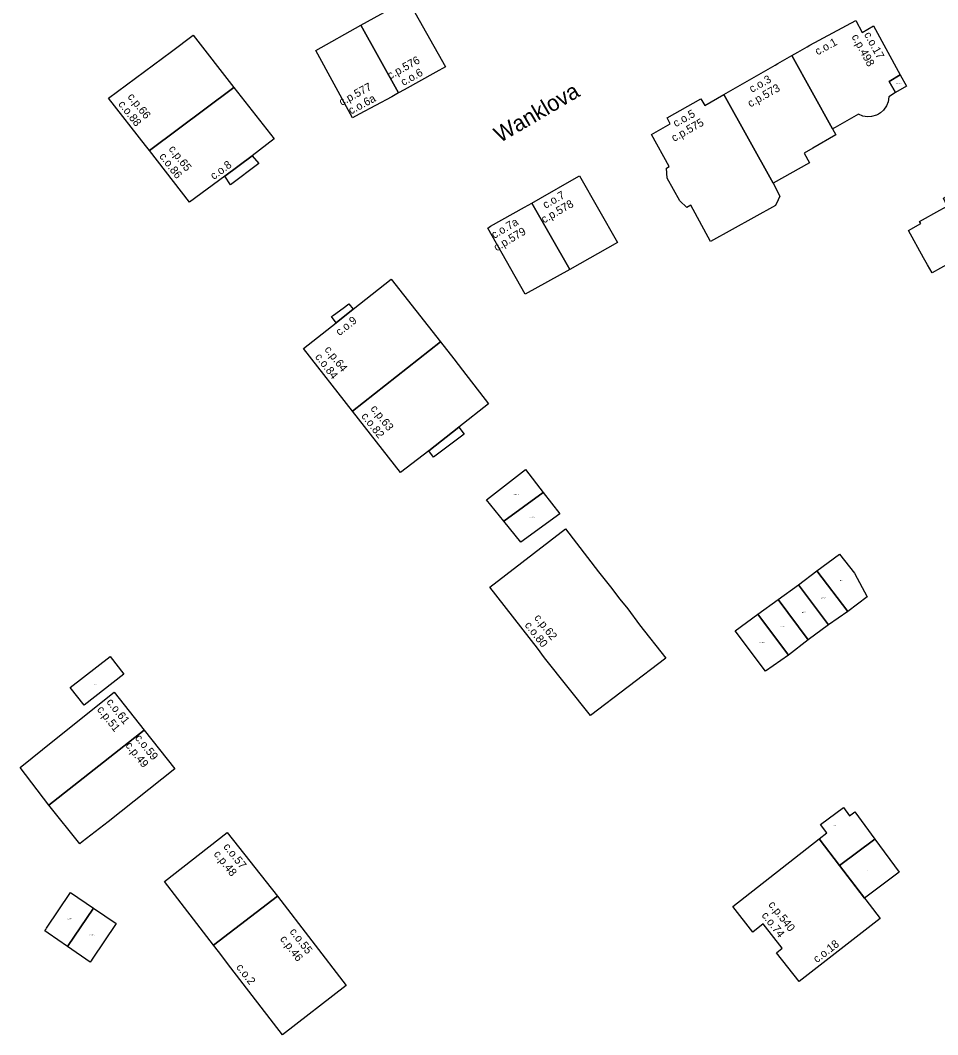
# Model space of a CAD drawing. Extents: x -600391 to -599491, y -1160176 to -1159402.
# Drawn here: x -600327.9 to -600213.3, y -1160067.8 to -1159941 of the extents above; entities that cross this region are included whole.
import ezdxf

# ---------------------------------------------------------------- set-up
doc = ezdxf.new("R2010")
doc.units = 0
for name, color, linetype in [('Level 10', 7, 'Continuous'), ('Level 11', 7, 'Continuous'), ('Level 12', 7, 'Continuous'), ('Level 24', 7, 'Continuous'), ('Level 25', 7, 'Continuous'), ('Level 61', 7, 'Continuous'), ('Level 62', 7, 'Continuous')]:
    doc.layers.add(name, color=color, linetype=linetype)

msp = doc.modelspace()

# ---------------------------------------------------------------- linework, layer by layer
at = {"layer": 'Level 61'}
for points in [[(-600285.36, -1159941.63), (-600279.55, -1159938.41)], [(-600279.55, -1159938.41), (-600274.78, -1159946.87)], [(-600229.25, -1159944.16), (-600223.53, -1159941.07)], [(-600223.53, -1159941.07), (-600222.73, -1159942.57)], [(-600290.98, -1159944.83), (-600285.36, -1159941.63)], [(-600285.36, -1159941.63), (-600280.65, -1159950.09)], [(-600280.65, -1159950.09), (-600285.36, -1159941.63)], [(-600222.73, -1159942.57), (-600221.32, -1159941.73)], [(-600221.32, -1159941.73), (-600217.98, -1159947.85)], [(-600309.01, -1159944.93), (-600306.29, -1159942.91)], [(-600306.29, -1159942.91), (-600301.22, -1159949.45)], [(-600312.4, -1159947.44), (-600309.01, -1159944.93)], [(-600286.39, -1159953.23), (-600290.98, -1159944.83)], [(-600230.77, -1159945.02), (-600229.6, -1159944.36)], [(-600229.6, -1159944.36), (-600229.25, -1159944.16)], [(-600233.25, -1159946.44), (-600231.52, -1159945.45)], [(-600231.52, -1159945.45), (-600230.77, -1159945.02)], [(-600231.52, -1159945.45), (-600226.43, -1159954.6)], [(-600226.43, -1159954.6), (-600231.52, -1159945.45)], [(-600316.88, -1159950.78), (-600312.4, -1159947.44)], [(-600275.98, -1159947.53), (-600279.95, -1159949.71)], [(-600274.78, -1159946.87), (-600275.98, -1159947.53)], [(-600240.02, -1159950.31), (-600233.6, -1159946.64)], [(-600233.6, -1159946.64), (-600233.25, -1159946.44)], [(-600219.36, -1159948.67), (-600217.98, -1159947.85)], [(-600217.98, -1159947.85), (-600219.36, -1159948.67)], [(-600218.56, -1159950.08), (-600219.36, -1159948.67)], [(-600219.36, -1159948.67), (-600218.56, -1159950.08)], [(-600217.98, -1159947.85), (-600217.19, -1159949.29)], [(-600301.22, -1159949.45), (-600311.77, -1159957.33)], [(-600311.77, -1159957.33), (-600301.22, -1159949.45)], [(-600301.22, -1159949.45), (-600296.21, -1159955.87)], [(-600279.95, -1159949.71), (-600280.65, -1159950.09)], [(-600218.56, -1159950.08), (-600219.4, -1159950.61)], [(-600217.19, -1159949.29), (-600218.56, -1159950.08)], [(-600312.28, -1159956.68), (-600316.88, -1159950.78)], [(-600281.5, -1159950.59), (-600285.57, -1159952.79)], [(-600280.65, -1159950.09), (-600281.5, -1159950.59)], [(-600247.1, -1159953.23), (-600242.88, -1159950.86)], [(-600242.88, -1159950.86), (-600242.4, -1159951.67)], [(-600242.4, -1159951.67), (-600240.02, -1159950.31)], [(-600233.84, -1159961.39), (-600240.02, -1159950.31)], [(-600240.02, -1159950.31), (-600233.84, -1159961.39)], [(-600219.48, -1159951.21), (-600219.7, -1159951.74)], [(-600219.4, -1159950.61), (-600219.48, -1159951.21)], [(-600220.44, -1159952.6), (-600220.68, -1159952.76)], [(-600220.05, -1159952.26), (-600220.44, -1159952.6)], [(-600219.7, -1159951.74), (-600220.05, -1159952.26)], [(-600285.57, -1159952.79), (-600286.39, -1159953.23)], [(-600246.71, -1159953.98), (-600247.1, -1159953.23)], [(-600223.18, -1159952.76), (-600226.09, -1159954.44)], [(-600222.62, -1159953), (-600223.18, -1159952.76)], [(-600222.04, -1159953.09), (-600222.62, -1159953)], [(-600221.54, -1159953.06), (-600222.04, -1159953.09)], [(-600220.93, -1159952.89), (-600221.54, -1159953.06)], [(-600220.68, -1159952.76), (-600220.93, -1159952.89)], [(-600249.03, -1159955.33), (-600246.71, -1159953.98)], [(-600226.09, -1159954.44), (-600226.43, -1159954.6)], [(-600226.43, -1159954.6), (-600226.02, -1159955.35)], [(-600296.21, -1159955.87), (-600298.92, -1159957.98)], [(-600246.84, -1159959.32), (-600249.03, -1159955.33)], [(-600226.02, -1159955.35), (-600228.9, -1159957.03)], [(-600311.77, -1159957.33), (-600312.28, -1159956.68)], [(-600306.75, -1159963.77), (-600311.77, -1159957.33)], [(-600228.9, -1159957.03), (-600229.98, -1159957.66)], [(-600229.98, -1159957.66), (-600229.31, -1159958.84)], [(-600302.36, -1159960.5), (-600298.92, -1159957.98)], [(-600298.92, -1159957.98), (-600302.36, -1159960.5)], [(-600298.1, -1159958.92), (-600301.63, -1159961.58)], [(-600298.92, -1159957.98), (-600298.1, -1159958.92)], [(-600229.31, -1159958.84), (-600233.84, -1159961.39)], [(-600247.15, -1159959.5), (-600246.84, -1159959.32)], [(-600247.07, -1159960.78), (-600247.15, -1159959.5)], [(-600302.36, -1159960.5), (-600306.75, -1159963.77)], [(-600301.63, -1159961.58), (-600302.36, -1159960.5)], [(-600262.91, -1159963.25), (-600258.7, -1159960.84)], [(-600258.7, -1159960.84), (-600258.03, -1159960.47)], [(-600258.03, -1159960.47), (-600253.31, -1159968.82)], [(-600245.49, -1159963.61), (-600247.07, -1159960.78)], [(-600233.84, -1159961.39), (-600232.99, -1159963.02)], [(-600264.92, -1159964.4), (-600264.01, -1159963.88)], [(-600264.01, -1159963.88), (-600262.91, -1159963.25)], [(-600259.23, -1159972.18), (-600264.01, -1159963.88)], [(-600264.01, -1159963.88), (-600259.23, -1159972.18)], [(-600244.64, -1159964.43), (-600245.49, -1159963.61)], [(-600233.2, -1159963.47), (-600233.56, -1159964.19)], [(-600232.99, -1159963.02), (-600233.2, -1159963.47)], [(-600269.15, -1159966.78), (-600264.92, -1159964.4)], [(-600244.14, -1159964.12), (-600244.64, -1159964.43)], [(-600241.69, -1159968.7), (-600244.14, -1159964.12)], [(-600233.56, -1159964.19), (-600241.69, -1159968.7)], [(-600215.57, -1159966.17), (-600213.02, -1159964.76)], [(-600216.94, -1159967.32), (-600215.4, -1159966.42)], [(-600215.4, -1159966.42), (-600215.57, -1159966.17)], [(-600269.51, -1159967.02), (-600269.15, -1159966.78)], [(-600264.82, -1159975.26), (-600269.51, -1159967.02)], [(-600215.04, -1159970.72), (-600216.94, -1159967.32)], [(-600253.31, -1159968.82), (-600259.23, -1159972.18)], [(-600214.55, -1159971.59), (-600215.04, -1159970.72)], [(-600213.99, -1159972.6), (-600214.55, -1159971.59)], [(-600211.91, -1159971.43), (-600213.99, -1159972.6)], [(-600259.23, -1159972.18), (-600264.82, -1159975.26)], [(-600286.32, -1159977.15), (-600281.56, -1159973.37)], [(-600281.56, -1159973.37), (-600275.41, -1159981.21)], [(-600287.57, -1159977), (-600286.88, -1159976.48)], [(-600286.88, -1159976.48), (-600286.32, -1159977.15)], [(-600289.01, -1159978.06), (-600288.78, -1159977.89)], [(-600288.78, -1159977.89), (-600287.57, -1159977)], [(-600288.44, -1159978.83), (-600286.32, -1159977.15)], [(-600286.32, -1159977.15), (-600288.44, -1159978.83)], [(-600292.51, -1159982.06), (-600288.44, -1159978.83)], [(-600288.44, -1159978.83), (-600289.01, -1159978.06)], [(-600275.41, -1159981.21), (-600286.4, -1159989.9)], [(-600286.4, -1159989.9), (-600275.41, -1159981.21)], [(-600275.41, -1159981.21), (-600273.76, -1159983.35)], [(-600286.4, -1159989.9), (-600292.51, -1159982.06)], [(-600273.76, -1159983.35), (-600272.66, -1159984.77)], [(-600272.66, -1159984.77), (-600269.43, -1159988.96)], [(-600269.43, -1159988.96), (-600273.11, -1159991.88)], [(-600280.39, -1159997.55), (-600286.4, -1159989.9)], [(-600276.88, -1159994.84), (-600273.11, -1159991.88)], [(-600273.11, -1159991.88), (-600276.88, -1159994.84)], [(-600273.11, -1159991.88), (-600272.46, -1159992.74)], [(-600272.46, -1159992.74), (-600276.27, -1159995.64)], [(-600276.88, -1159994.84), (-600280.39, -1159997.55)], [(-600276.27, -1159995.64), (-600276.88, -1159994.84)], [(-600269.64, -1160000.94), (-600264.77, -1159997.17)], [(-600264.77, -1159997.17), (-600262.56, -1160000.05)], [(-600267.48, -1160003.63), (-600262.56, -1160000.05)], [(-600262.56, -1160000.05), (-600267.48, -1160003.63)], [(-600262.56, -1160000.05), (-600260.48, -1160002.7)], [(-600267.48, -1160003.63), (-600269.64, -1160000.94)], [(-600260.48, -1160002.7), (-600265.37, -1160006.26)], [(-600269.24, -1160011.85), (-600259.79, -1160004.57)], [(-600265.37, -1160006.26), (-600267.48, -1160003.63)], [(-600259.79, -1160004.57), (-600255.66, -1160009.94)], [(-600228.38, -1160009.82), (-600225.57, -1160007.75)], [(-600225.57, -1160007.75), (-600223.68, -1160010.11)], [(-600255.66, -1160009.94), (-600254.18, -1160011.82)], [(-600230.69, -1160011.59), (-600228.38, -1160009.82)], [(-600224.53, -1160014.89), (-600228.38, -1160009.82)], [(-600228.38, -1160009.82), (-600224.53, -1160014.89)], [(-600223.68, -1160010.11), (-600222.11, -1160013.06)], [(-600263.28, -1160019.49), (-600269.24, -1160011.85)], [(-600254.18, -1160011.82), (-600252.98, -1160013.36)], [(-600233.22, -1160013.43), (-600230.69, -1160011.59)], [(-600230.69, -1160011.59), (-600226.92, -1160016.58)], [(-600226.92, -1160016.58), (-600230.69, -1160011.59)], [(-600252.98, -1160013.36), (-600252.02, -1160014.58)], [(-600235.75, -1160015.25), (-600233.22, -1160013.43)], [(-600229.48, -1160018.47), (-600233.22, -1160013.43)], [(-600233.22, -1160013.43), (-600229.48, -1160018.47)], [(-600222.11, -1160013.06), (-600224.53, -1160014.89)], [(-600252.02, -1160014.58), (-600250.54, -1160016.56)], [(-600238.6, -1160017.34), (-600235.75, -1160015.25)], [(-600235.75, -1160015.25), (-600231.94, -1160020.35)], [(-600231.94, -1160020.35), (-600235.75, -1160015.25)], [(-600224.53, -1160014.89), (-600226.92, -1160016.58)], [(-600250.54, -1160016.56), (-600247.25, -1160020.76)], [(-600226.92, -1160016.58), (-600229.48, -1160018.47)], [(-600234.79, -1160022.38), (-600238.6, -1160017.34)], [(-600229.48, -1160018.47), (-600231.94, -1160020.35)], [(-600262.41, -1160020.69), (-600263.28, -1160019.49)], [(-600321.66, -1160024.41), (-600316.69, -1160020.53)], [(-600316.69, -1160020.53), (-600314.97, -1160022.74)], [(-600256.66, -1160027.92), (-600262.41, -1160020.69)], [(-600247.25, -1160020.76), (-600256.66, -1160027.92)], [(-600231.94, -1160020.35), (-600234.79, -1160022.38)], [(-600314.97, -1160022.74), (-600319.94, -1160026.61)], [(-600319.94, -1160026.61), (-600321.66, -1160024.41)], [(-600323.64, -1160030.95), (-600316.19, -1160025)], [(-600316.19, -1160025), (-600312.45, -1160029.73)], [(-600324.36, -1160039.09), (-600312.45, -1160029.73)], [(-600312.45, -1160029.73), (-600324.36, -1160039.09)], [(-600312.45, -1160029.73), (-600308.62, -1160034.58)], [(-600327.91, -1160034.39), (-600323.64, -1160030.95)], [(-600324.36, -1160039.09), (-600327.91, -1160034.39)], [(-600308.62, -1160034.58), (-600316.93, -1160041.19)], [(-600320.47, -1160043.95), (-600324.36, -1160039.09)], [(-600227.94, -1160041.51), (-600225.07, -1160039.38)], [(-600225.07, -1160039.38), (-600224.3, -1160040.44)], [(-600224.3, -1160040.44), (-600223.62, -1160039.93)], [(-600223.62, -1160039.93), (-600221.13, -1160043.34)], [(-600316.93, -1160041.19), (-600320.18, -1160043.69)], [(-600309.9, -1160048.65), (-600302.05, -1160042.51)], [(-600302.05, -1160042.51), (-600295.77, -1160050.46)], [(-600228.11, -1160043.33), (-600227.15, -1160042.56)], [(-600227.15, -1160042.56), (-600227.94, -1160041.51)], [(-600320.18, -1160043.69), (-600320.47, -1160043.95)], [(-600238.89, -1160051.75), (-600228.11, -1160043.33)], [(-600225.56, -1160046.66), (-600228.11, -1160043.33)], [(-600228.11, -1160043.33), (-600225.56, -1160046.66)], [(-600225.56, -1160046.66), (-600221.13, -1160043.34)], [(-600221.13, -1160043.34), (-600225.56, -1160046.66)], [(-600221.13, -1160043.34), (-600218.08, -1160047.46)], [(-600222.45, -1160050.71), (-600225.56, -1160046.66)], [(-600225.56, -1160046.66), (-600220.47, -1160053.29)], [(-600218.08, -1160047.46), (-600222.45, -1160050.71)], [(-600303.75, -1160056.62), (-600309.9, -1160048.65)], [(-600324.62, -1160054.47), (-600321.62, -1160050.04)], [(-600321.62, -1160050.04), (-600318.76, -1160051.98)], [(-600303.75, -1160056.62), (-600295.77, -1160050.46)], [(-600295.77, -1160050.46), (-600303.75, -1160056.62)], [(-600295.77, -1160050.46), (-600287.21, -1160061.63)], [(-600318.76, -1160051.98), (-600322.02, -1160056.78)], [(-600322.02, -1160056.78), (-600318.76, -1160051.98)], [(-600318.76, -1160051.98), (-600315.93, -1160053.9)], [(-600236.4, -1160054.97), (-600238.89, -1160051.75)], [(-600315.93, -1160053.9), (-600318.93, -1160058.37)], [(-600235.08, -1160053.94), (-600236.4, -1160054.97)], [(-600232.72, -1160056.96), (-600235.08, -1160053.94)], [(-600220.47, -1160053.29), (-600230.59, -1160061.13)], [(-600324.84, -1160054.8), (-600324.73, -1160054.64)], [(-600324.41, -1160055.1), (-600324.84, -1160054.8)], [(-600324.73, -1160054.64), (-600324.62, -1160054.47)], [(-600322.02, -1160056.78), (-600324.41, -1160055.1)], [(-600319.16, -1160058.72), (-600322.02, -1160056.78)], [(-600303.16, -1160057.39), (-600303.75, -1160056.62)], [(-600301.6, -1160059.43), (-600303.16, -1160057.39)], [(-600233.43, -1160057.54), (-600232.72, -1160056.96)], [(-600230.59, -1160061.13), (-600233.43, -1160057.54)], [(-600319.04, -1160058.54), (-600319.16, -1160058.72)], [(-600318.93, -1160058.37), (-600319.04, -1160058.54)], [(-600295.15, -1160067.79), (-600301.6, -1160059.43)], [(-600287.21, -1160061.63), (-600295.15, -1160067.79)]]:
    msp.add_lwpolyline(points, dxfattribs=at)
at = {"layer": 'Level 62'}
for points in [[(-600285.36, -1159941.63), (-600279.55, -1159938.41), (-600274.78, -1159946.87), (-600275.98, -1159947.53), (-600279.95, -1159949.71), (-600280.65, -1159950.09), (-600285.36, -1159941.63)], [(-600230.77, -1159945.02), (-600229.6, -1159944.36), (-600229.25, -1159944.16), (-600223.53, -1159941.07), (-600222.73, -1159942.57), (-600221.32, -1159941.73), (-600217.98, -1159947.85), (-600219.36, -1159948.67), (-600218.56, -1159950.08), (-600219.4, -1159950.61), (-600219.48, -1159951.21), (-600219.7, -1159951.74), (-600220.05, -1159952.26), (-600220.44, -1159952.6), (-600220.68, -1159952.76), (-600220.93, -1159952.89), (-600221.54, -1159953.06), (-600222.04, -1159953.09), (-600222.62, -1159953), (-600223.18, -1159952.76), (-600226.09, -1159954.44), (-600226.43, -1159954.6), (-600231.52, -1159945.45), (-600230.77, -1159945.02)], [(-600281.5, -1159950.59), (-600285.57, -1159952.79), (-600286.39, -1159953.23), (-600290.98, -1159944.83), (-600285.36, -1159941.63), (-600280.65, -1159950.09), (-600281.5, -1159950.59)], [(-600301.22, -1159949.45), (-600311.77, -1159957.33), (-600312.28, -1159956.68), (-600316.88, -1159950.78), (-600312.4, -1159947.44), (-600309.01, -1159944.93), (-600306.29, -1159942.91), (-600301.22, -1159949.45)], [(-600233.6, -1159946.64), (-600233.25, -1159946.44), (-600231.52, -1159945.45), (-600226.43, -1159954.6), (-600226.02, -1159955.35), (-600228.9, -1159957.03), (-600229.98, -1159957.66), (-600229.31, -1159958.84), (-600233.84, -1159961.39), (-600240.02, -1159950.31), (-600233.6, -1159946.64)], [(-600217.98, -1159947.85), (-600217.19, -1159949.29), (-600218.56, -1159950.08), (-600219.36, -1159948.67), (-600217.98, -1159947.85)], [(-600301.22, -1159949.45), (-600296.21, -1159955.87), (-600298.92, -1159957.98), (-600302.36, -1159960.5), (-600306.75, -1159963.77), (-600311.77, -1159957.33), (-600301.22, -1159949.45)], [(-600233.2, -1159963.47), (-600233.56, -1159964.19), (-600241.69, -1159968.7), (-600244.14, -1159964.12), (-600244.64, -1159964.43), (-600245.49, -1159963.61), (-600247.07, -1159960.78), (-600247.15, -1159959.5), (-600246.84, -1159959.32), (-600249.03, -1159955.33), (-600246.71, -1159953.98), (-600247.1, -1159953.23), (-600242.88, -1159950.86), (-600242.4, -1159951.67), (-600240.02, -1159950.31), (-600233.84, -1159961.39), (-600232.99, -1159963.02), (-600233.2, -1159963.47)], [(-600298.92, -1159957.98), (-600298.1, -1159958.92), (-600301.63, -1159961.58), (-600302.36, -1159960.5), (-600298.92, -1159957.98)], [(-600206.09, -1159959.69), (-600204.75, -1159962.19), (-600203.41, -1159964.59), (-600202.55, -1159966.16), (-600211.91, -1159971.43), (-600213.99, -1159972.6), (-600214.55, -1159971.59), (-600215.04, -1159970.72), (-600216.94, -1159967.32), (-600215.4, -1159966.42), (-600215.57, -1159966.17), (-600213.02, -1159964.76), (-600212.11, -1159964.26), (-600212.57, -1159963.25), (-600206.09, -1159959.69)], [(-600264.01, -1159963.88), (-600262.91, -1159963.25), (-600258.7, -1159960.84), (-600258.03, -1159960.47), (-600253.31, -1159968.82), (-600259.23, -1159972.18), (-600264.01, -1159963.88)], [(-600264.01, -1159963.88), (-600259.23, -1159972.18), (-600264.82, -1159975.26), (-600269.51, -1159967.02), (-600269.15, -1159966.78), (-600264.92, -1159964.4), (-600264.01, -1159963.88)], [(-600286.32, -1159977.15), (-600281.56, -1159973.37), (-600275.41, -1159981.21), (-600286.4, -1159989.9), (-600292.51, -1159982.06), (-600288.44, -1159978.83), (-600286.32, -1159977.15)], [(-600286.32, -1159977.15), (-600288.44, -1159978.83), (-600289.01, -1159978.06), (-600288.78, -1159977.89), (-600287.57, -1159977), (-600286.88, -1159976.48), (-600286.32, -1159977.15)], [(-600273.11, -1159991.88), (-600276.88, -1159994.84), (-600280.39, -1159997.55), (-600286.4, -1159989.9), (-600275.41, -1159981.21), (-600273.76, -1159983.35), (-600272.66, -1159984.77), (-600269.43, -1159988.96), (-600273.11, -1159991.88)], [(-600273.11, -1159991.88), (-600272.46, -1159992.74), (-600276.27, -1159995.64), (-600276.88, -1159994.84), (-600273.11, -1159991.88)], [(-600267.48, -1160003.63), (-600269.64, -1160000.94), (-600264.77, -1159997.17), (-600262.56, -1160000.05), (-600267.48, -1160003.63)], [(-600267.48, -1160003.63), (-600262.56, -1160000.05), (-600260.48, -1160002.7), (-600265.37, -1160006.26), (-600267.48, -1160003.63)], [(-600254.18, -1160011.82), (-600252.98, -1160013.36), (-600252.02, -1160014.58), (-600250.54, -1160016.56), (-600247.25, -1160020.76), (-600256.66, -1160027.92), (-600262.41, -1160020.69), (-600263.28, -1160019.49), (-600269.24, -1160011.85), (-600259.79, -1160004.57), (-600255.66, -1160009.94), (-600254.18, -1160011.82)], [(-600224.53, -1160014.89), (-600228.38, -1160009.82), (-600225.57, -1160007.75), (-600223.68, -1160010.11), (-600222.11, -1160013.06), (-600224.53, -1160014.89)], [(-600224.53, -1160014.89), (-600226.92, -1160016.58), (-600230.69, -1160011.59), (-600228.38, -1160009.82), (-600224.53, -1160014.89)], [(-600229.48, -1160018.47), (-600233.22, -1160013.43), (-600230.69, -1160011.59), (-600226.92, -1160016.58), (-600229.48, -1160018.47)], [(-600231.94, -1160020.35), (-600235.75, -1160015.25), (-600233.22, -1160013.43), (-600229.48, -1160018.47), (-600231.94, -1160020.35)], [(-600231.94, -1160020.35), (-600234.79, -1160022.38), (-600238.6, -1160017.34), (-600235.75, -1160015.25), (-600231.94, -1160020.35)], [(-600314.97, -1160022.74), (-600319.94, -1160026.61), (-600321.66, -1160024.41), (-600316.69, -1160020.53), (-600314.97, -1160022.74)], [(-600327.91, -1160034.39), (-600323.64, -1160030.95), (-600316.19, -1160025), (-600312.45, -1160029.73), (-600324.36, -1160039.09), (-600327.91, -1160034.39)], [(-600312.45, -1160029.73), (-600308.62, -1160034.58), (-600316.93, -1160041.19), (-600320.18, -1160043.69), (-600320.47, -1160043.95), (-600324.36, -1160039.09), (-600312.45, -1160029.73)], [(-600221.13, -1160043.34), (-600225.56, -1160046.66), (-600228.11, -1160043.33), (-600227.15, -1160042.56), (-600227.94, -1160041.51), (-600225.07, -1160039.38), (-600224.3, -1160040.44), (-600223.62, -1160039.93), (-600221.13, -1160043.34)], [(-600295.77, -1160050.46), (-600303.75, -1160056.62), (-600309.9, -1160048.65), (-600302.05, -1160042.51), (-600295.77, -1160050.46)], [(-600220.47, -1160053.29), (-600230.59, -1160061.13), (-600233.43, -1160057.54), (-600232.72, -1160056.96), (-600235.08, -1160053.94), (-600236.4, -1160054.97), (-600238.89, -1160051.75), (-600228.11, -1160043.33), (-600225.56, -1160046.66), (-600220.47, -1160053.29)], [(-600225.56, -1160046.66), (-600221.13, -1160043.34), (-600218.08, -1160047.46), (-600222.45, -1160050.71), (-600225.56, -1160046.66)], [(-600324.73, -1160054.64), (-600324.62, -1160054.47), (-600321.62, -1160050.04), (-600318.76, -1160051.98), (-600322.02, -1160056.78), (-600324.41, -1160055.1), (-600324.84, -1160054.8), (-600324.73, -1160054.64)], [(-600295.15, -1160067.79), (-600301.6, -1160059.43), (-600303.16, -1160057.39), (-600303.75, -1160056.62), (-600295.77, -1160050.46), (-600287.21, -1160061.63), (-600295.15, -1160067.79)], [(-600322.02, -1160056.78), (-600318.76, -1160051.98), (-600315.93, -1160053.9), (-600318.93, -1160058.37), (-600319.04, -1160058.54), (-600319.16, -1160058.72), (-600322.02, -1160056.78)]]:
    msp.add_lwpolyline(points, dxfattribs=at)

# ---------------------------------------------------------------- texts
at = {"layer": 'Level 10'}
for s, rotation, p in [('c.o.1', 28.3795, (-600228.3, -1159945.44)), ('c.o.17', 298.6255, (-600222.52, -1159942.8)), ('c.o.6', 29.0513, (-600280.04, -1159949.26)), ('c.o.3', 29.6056, (-600236.5, -1159950.12)), ('c.o.88', 308.2795, (-600315.73, -1159951.54)), ('c.o.6a', 28.4564, (-600286.59, -1159952.83)), ('c.o.5', 29.3206, (-600246.01, -1159954.42)), ('c.o.86', 307.6549, (-600310.61, -1159958.05)), ('c.o.8', 36.4849, (-600303.73, -1159961.01)), ('c.o.7', 29.6774, (-600262.29, -1159964.61)), ('c.o.7a', 30.7427, (-600268.7, -1159968.37)), ('c.o.9', 38.3976, (-600288.03, -1159980.52)), ('c.o.84', 307.8921, (-600291.14, -1159983.11)), ('c.o.82', 308.1936, (-600285.37, -1159990.52)), ('c.o.80', 308.0549, (-600264.95, -1160016.63)), ('c.o.61', 308.3323, (-600317.2, -1160026.24)), ('c.o.59', 308.2956, (-600313.64, -1160030.73)), ('c.o.57', 308.3082, (-600302.6, -1160044.32)), ('c.o.74', 308.0102, (-600235.35, -1160052.89)), ('c.o.55', 307.4669, (-600294.31, -1160054.92)), ('c.o.18', 37.7649, (-600228.38, -1160058.87)), ('c.o.2', 307.6388, (-600300.99, -1160059.37))]:
    msp.add_text(s, height=1, rotation=rotation, dxfattribs=at).set_placement(p)
at = {"layer": 'Level 11'}
msp.add_text('Wanklova', height=2, rotation=30.3991, dxfattribs=at).set_placement((-600267.97, -1159956.39))
at = {"layer": 'Level 12'}
for s, rotation, p in [('c.p.498', 298.6255, (-600224.08, -1159943.08)), ('c.p.576', 29.0513, (-600281.71, -1159948.45)), ('c.p.577', 28.4564, (-600287.76, -1159951.75)), ('c.p.573', 29.6056, (-600236.69, -1159951.95)), ('c.p.66', 308.2795, (-600314.56, -1159950.61)), ('c.p.575', 29.3206, (-600246.22, -1159956.25)), ('c.p.65', 307.6549, (-600309.43, -1159957.13)), ('c.p.578', 29.6774, (-600262.49, -1159966.44)), ('c.p.579', 30.7427, (-600268.4, -1159969.93)), ('c.p.64', 307.8921, (-600289.96, -1159982.19)), ('c.p.63', 308.1936, (-600284.21, -1159989.58)), ('c.p.62', 308.0549, (-600263.77, -1160015.71)), ('c.p.51', 308.3323, (-600318.38, -1160027.18)), ('c.p.49', 308.2956, (-600314.83, -1160031.66)), ('c.p.48', 308.3082, (-600303.8, -1160045.24)), ('c.p.540', 308.0102, (-600234.5, -1160051.55)), ('c.p.46', 307.4669, (-600295.51, -1160055.84))]:
    msp.add_text(s, height=1, rotation=rotation, dxfattribs=at).set_placement(p)
at = {"layer": 'Level 24'}
for s, p in [('c.z.342', (-600318.72, -1160024.1)), ('c.z.267', (-600226.41, -1160041.69)), ('c.z.208', (-600222.14, -1160047.25))]:
    msp.add_text(s, height=0.1, dxfattribs=at).set_placement(p)
at = {"layer": 'Level 25'}
for s, p in [('c.pp.498_A', (-600218.51, -1159948.98)), ('c.pp.62_B', (-600266.28, -1160000.34)), ('c.pp.62_A', (-600264.26, -1160003.17)), ('c.pp.62_H', (-600225.59, -1160011.06)), ('c.pp.62_G', (-600227.89, -1160013.26)), ('c.pp.62_F', (-600230.34, -1160015.05)), ('c.pp.62_E', (-600232.91, -1160016.86)), ('c.pp.62_D', (-600235.56, -1160018.83)), ('c.pp.49_A', (-600322.07, -1160053.36)), ('c.pp.48_A', (-600319.28, -1160055.38))]:
    msp.add_text(s, height=0.1, dxfattribs=at).set_placement(p)

doc.saveas('drawing.dxf')
